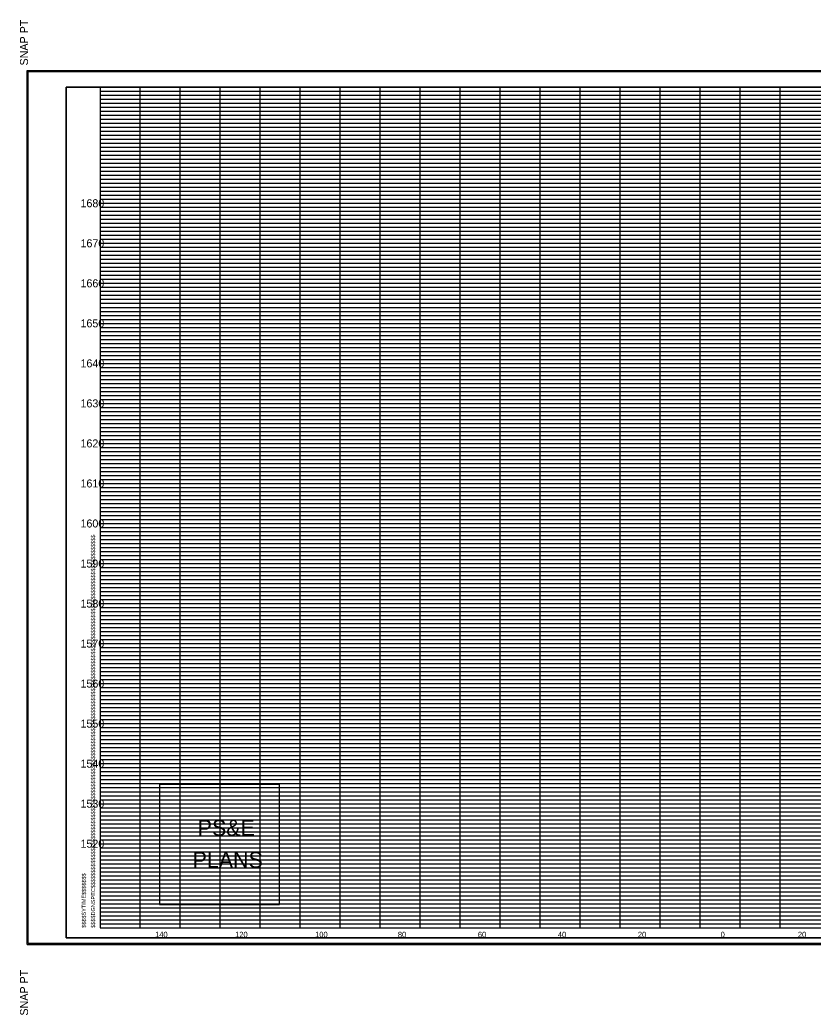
# Model space of a CAD drawing. Extents: x 980 to 1380, y 1248 to 3387.
# Drawn here: x 979.9 to 1178.2, y 1248.2 to 1496.8 of the extents above; entities that cross this region are included whole.
import ezdxf

# ---------------------------------------------------------------- set-up
doc = ezdxf.new("R2010")
doc.units = 0
for name, color, linetype in [('DESIGN - SHEET - Corner Text', 7, 'Continuous'), ('DESIGN - SHEET - Light Grid', 7, 'Continuous'), ('DESIGN - SHEET - Linework', 7, 'Continuous'), ('DESIGN - SHEET - Plot Shape', 7, 'Continuous'), ('DESIGN - TYPICAL - Text', 7, 'Continuous')]:
    doc.layers.add(name, color=color, linetype=linetype)

# ---------------------------------------------------------------- blocks, each defined once
blk = doc.blocks.new('XSTSHT')
at = {"layer": 'DESIGN - SHEET - Light Grid'}
for p, q in [((0, 20.9), (8, 20.9)), ((8, 20.9), (16, 20.9)), ((16, 20.9), (24, 20.9)), ((0, 20.8), (8, 20.8)), ((0, 20.7), (8, 20.7)), ((8, 20.8), (16, 20.8)), ((8, 20.7), (16, 20.7)), ((16, 20.8), (24, 20.8)), ((16, 20.7), (24, 20.7)), ((0, 20.6), (8, 20.6)), ((0, 20.5), (8, 20.5)), ((0, 20.4), (8, 20.4)), ((8, 20.6), (16, 20.6)), ((8, 20.5), (16, 20.5)), ((8, 20.4), (16, 20.4)), ((16, 20.6), (24, 20.6)), ((16, 20.5), (24, 20.5)), ((16, 20.4), (24, 20.4)), ((0, 20.3), (8, 20.3)), ((0, 20.2), (8, 20.2)), ((8, 20.3), (16, 20.3)), ((8, 20.2), (16, 20.2)), ((16, 20.3), (24, 20.3)), ((16, 20.2), (24, 20.2)), ((0, 20.1), (8, 20.1)), ((0, 19.9), (8, 19.9)), ((8, 20.1), (16, 20.1)), ((8, 19.9), (16, 19.9)), ((16, 20.1), (24, 20.1)), ((16, 19.9), (24, 19.9)), ((0, 19.8), (8, 19.8)), ((0, 19.7), (8, 19.7)), ((8, 19.8), (16, 19.8)), ((8, 19.7), (16, 19.7)), ((16, 19.8), (24, 19.8)), ((16, 19.7), (24, 19.7)), ((0, 19.6), (8, 19.6)), ((0, 19.5), (8, 19.5)), ((0, 19.4), (8, 19.4)), ((8, 19.6), (16, 19.6)), ((8, 19.5), (16, 19.5)), ((8, 19.4), (16, 19.4)), ((16, 19.6), (24, 19.6)), ((16, 19.5), (24, 19.5)), ((16, 19.4), (24, 19.4)), ((0, 19.3), (8, 19.3)), ((0, 19.2), (8, 19.2)), ((8, 19.3), (16, 19.3)), ((8, 19.2), (16, 19.2)), ((16, 19.3), (24, 19.3)), ((16, 19.2), (24, 19.2)), ((0, 19.1), (8, 19.1)), ((0, 18.9), (8, 18.9)), ((8, 19.1), (16, 19.1)), ((8, 18.9), (16, 18.9)), ((16, 19.1), (24, 19.1)), ((16, 18.9), (24, 18.9)), ((0, 18.8), (8, 18.8)), ((0, 18.7), (8, 18.7)), ((8, 18.8), (16, 18.8)), ((8, 18.7), (16, 18.7)), ((16, 18.8), (24, 18.8)), ((16, 18.7), (24, 18.7)), ((0, 18.6), (8, 18.6)), ((0, 18.5), (8, 18.5)), ((0, 18.4), (8, 18.4)), ((8, 18.6), (16, 18.6)), ((8, 18.5), (16, 18.5)), ((8, 18.4), (16, 18.4)), ((16, 18.6), (24, 18.6)), ((16, 18.5), (24, 18.5)), ((16, 18.4), (24, 18.4)), ((0, 18.3), (8, 18.3)), ((0, 18.2), (8, 18.2)), ((8, 18.3), (16, 18.3)), ((8, 18.2), (16, 18.2)), ((16, 18.3), (24, 18.3)), ((16, 18.2), (24, 18.2)), ((0, 18.1), (8, 18.1)), ((8, 18.1), (16, 18.1)), ((16, 18.1), (24, 18.1)), ((0, 17.9), (8, 17.9)), ((0, 17.8), (8, 17.8)), ((0, 17.7), (8, 17.7)), ((8, 17.9), (16, 17.9)), ((8, 17.8), (16, 17.8)), ((8, 17.7), (16, 17.7)), ((16, 17.9), (24, 17.9)), ((16, 17.8), (24, 17.8)), ((16, 17.7), (24, 17.7)), ((0, 17.6), (8, 17.6)), ((0, 17.5), (8, 17.5)), ((8, 17.6), (16, 17.6)), ((8, 17.5), (16, 17.5)), ((16, 17.6), (24, 17.6)), ((16, 17.5), (24, 17.5)), ((0, 17.4), (8, 17.4)), ((0, 17.3), (8, 17.3)), ((0, 17.2), (8, 17.2)), ((8, 17.4), (16, 17.4)), ((8, 17.3), (16, 17.3)), ((8, 17.2), (16, 17.2)), ((16, 17.4), (24, 17.4)), ((16, 17.3), (24, 17.3)), ((16, 17.2), (24, 17.2)), ((0, 17.1), (8, 17.1)), ((8, 17.1), (16, 17.1)), ((16, 17.1), (24, 17.1)), ((0, 16.9), (8, 16.9)), ((0, 16.8), (8, 16.8)), ((0, 16.7), (8, 16.7)), ((8, 16.9), (16, 16.9)), ((8, 16.8), (16, 16.8)), ((8, 16.7), (16, 16.7)), ((16, 16.9), (24, 16.9)), ((16, 16.8), (24, 16.8)), ((16, 16.7), (24, 16.7)), ((0, 16.6), (8, 16.6)), ((0, 16.5), (8, 16.5)), ((8, 16.6), (16, 16.6)), ((8, 16.5), (16, 16.5)), ((16, 16.6), (24, 16.6)), ((16, 16.5), (24, 16.5)), ((0, 16.4), (8, 16.4)), ((0, 16.3), (8, 16.3)), ((0, 16.2), (8, 16.2)), ((8, 16.4), (16, 16.4)), ((8, 16.3), (16, 16.3)), ((8, 16.2), (16, 16.2)), ((16, 16.4), (24, 16.4)), ((16, 16.3), (24, 16.3)), ((16, 16.2), (24, 16.2)), ((0, 16.1), (8, 16.1)), ((8, 16.1), (16, 16.1)), ((16, 16.1), (24, 16.1)), ((0, 15.9), (8, 15.9)), ((0, 15.8), (8, 15.8)), ((0, 15.7), (8, 15.7)), ((8, 15.9), (16, 15.9)), ((8, 15.8), (16, 15.8)), ((8, 15.7), (16, 15.7)), ((16, 15.9), (24, 15.9)), ((16, 15.8), (24, 15.8)), ((16, 15.7), (24, 15.7)), ((0, 15.6), (8, 15.6)), ((0, 15.5), (8, 15.5)), ((8, 15.6), (16, 15.6)), ((8, 15.5), (16, 15.5)), ((16, 15.6), (24, 15.6)), ((16, 15.5), (24, 15.5)), ((0, 15.4), (8, 15.4)), ((0, 15.3), (8, 15.3)), ((0, 15.2), (8, 15.2)), ((8, 15.4), (16, 15.4)), ((8, 15.3), (16, 15.3)), ((8, 15.2), (16, 15.2)), ((16, 15.4), (24, 15.4)), ((16, 15.3), (24, 15.3)), ((16, 15.2), (24, 15.2)), ((0, 15.1), (8, 15.1)), ((8, 15.1), (16, 15.1)), ((16, 15.1), (24, 15.1)), ((0, 14.9), (8, 14.9)), ((0, 14.8), (8, 14.8)), ((0, 14.7), (8, 14.7)), ((8, 14.9), (16, 14.9)), ((8, 14.8), (16, 14.8)), ((8, 14.7), (16, 14.7)), ((16, 14.9), (24, 14.9)), ((16, 14.8), (24, 14.8)), ((16, 14.7), (24, 14.7)), ((0, 14.6), (8, 14.6)), ((0, 14.5), (8, 14.5)), ((8, 14.6), (16, 14.6)), ((8, 14.5), (16, 14.5)), ((16, 14.6), (24, 14.6)), ((16, 14.5), (24, 14.5)), ((0, 14.4), (8, 14.4)), ((0, 14.3), (8, 14.3)), ((0, 14.2), (8, 14.2)), ((8, 14.4), (16, 14.4)), ((8, 14.3), (16, 14.3)), ((8, 14.2), (16, 14.2)), ((16, 14.4), (24, 14.4)), ((16, 14.3), (24, 14.3)), ((16, 14.2), (24, 14.2)), ((0, 14.1), (8, 14.1)), ((8, 14.1), (16, 14.1)), ((16, 14.1), (24, 14.1)), ((0, 13.9), (8, 13.9)), ((0, 13.8), (8, 13.8)), ((0, 13.7), (8, 13.7)), ((8, 13.9), (16, 13.9)), ((8, 13.8), (16, 13.8)), ((8, 13.7), (16, 13.7)), ((16, 13.9), (24, 13.9)), ((16, 13.8), (24, 13.8)), ((16, 13.7), (24, 13.7)), ((0, 13.6), (8, 13.6)), ((0, 13.5), (8, 13.5)), ((8, 13.6), (16, 13.6)), ((8, 13.5), (16, 13.5)), ((16, 13.6), (24, 13.6)), ((16, 13.5), (24, 13.5)), ((0, 13.4), (8, 13.4)), ((0, 13.3), (8, 13.3)), ((0, 13.2), (8, 13.2)), ((8, 13.4), (16, 13.4)), ((8, 13.3), (16, 13.3)), ((8, 13.2), (16, 13.2)), ((16, 13.4), (24, 13.4)), ((16, 13.3), (24, 13.3)), ((16, 13.2), (24, 13.2)), ((0, 13.1), (8, 13.1)), ((8, 13.1), (16, 13.1)), ((16, 13.1), (24, 13.1)), ((0, 12.9), (8, 12.9)), ((0, 12.8), (8, 12.8)), ((0, 12.7), (8, 12.7)), ((8, 12.9), (16, 12.9)), ((8, 12.8), (16, 12.8)), ((8, 12.7), (16, 12.7)), ((16, 12.9), (24, 12.9)), ((16, 12.8), (24, 12.8)), ((16, 12.7), (24, 12.7)), ((0, 12.6), (8, 12.6)), ((0, 12.5), (8, 12.5)), ((8, 12.6), (16, 12.6)), ((8, 12.5), (16, 12.5)), ((16, 12.6), (24, 12.6)), ((16, 12.5), (24, 12.5)), ((0, 12.4), (8, 12.4)), ((0, 12.3), (8, 12.3)), ((0, 12.2), (8, 12.2)), ((8, 12.4), (16, 12.4)), ((8, 12.3), (16, 12.3)), ((8, 12.2), (16, 12.2)), ((16, 12.4), (24, 12.4)), ((16, 12.3), (24, 12.3)), ((16, 12.2), (24, 12.2)), ((0, 12.1), (8, 12.1)), ((8, 12.1), (16, 12.1)), ((16, 12.1), (24, 12.1)), ((0, 11.9), (8, 11.9)), ((0, 11.8), (8, 11.8)), ((0, 11.7), (8, 11.7)), ((8, 11.9), (16, 11.9)), ((8, 11.8), (16, 11.8)), ((8, 11.7), (16, 11.7)), ((16, 11.9), (24, 11.9)), ((16, 11.8), (24, 11.8)), ((16, 11.7), (24, 11.7)), ((0, 11.6), (8, 11.6)), ((0, 11.5), (8, 11.5)), ((8, 11.6), (16, 11.6)), ((8, 11.5), (16, 11.5)), ((16, 11.6), (24, 11.6)), ((16, 11.5), (24, 11.5)), ((0, 11.4), (8, 11.4)), ((0, 11.3), (8, 11.3)), ((0, 11.2), (8, 11.2)), ((8, 11.4), (16, 11.4)), ((8, 11.3), (16, 11.3)), ((8, 11.2), (16, 11.2)), ((16, 11.4), (24, 11.4)), ((16, 11.3), (24, 11.3)), ((16, 11.2), (24, 11.2)), ((0, 11.1), (8, 11.1)), ((8, 11.1), (16, 11.1)), ((16, 11.1), (24, 11.1)), ((0, 10.9), (8, 10.9)), ((0, 10.8), (8, 10.8)), ((0, 10.7), (8, 10.7)), ((8, 10.9), (16, 10.9)), ((8, 10.8), (16, 10.8)), ((8, 10.7), (16, 10.7)), ((16, 10.9), (24, 10.9)), ((16, 10.8), (24, 10.8)), ((16, 10.7), (24, 10.7)), ((0, 10.6), (8, 10.6)), ((0, 10.5), (8, 10.5)), ((8, 10.6), (16, 10.6)), ((8, 10.5), (16, 10.5)), ((16, 10.6), (24, 10.6)), ((16, 10.5), (24, 10.5)), ((0, 10.4), (8, 10.4)), ((0, 10.3), (8, 10.3)), ((0, 10.2), (8, 10.2)), ((8, 10.4), (16, 10.4)), ((8, 10.3), (16, 10.3)), ((8, 10.2), (16, 10.2)), ((16, 10.4), (24, 10.4)), ((16, 10.3), (24, 10.3)), ((16, 10.2), (24, 10.2)), ((0, 10.1), (8, 10.1)), ((8, 10.1), (16, 10.1)), ((16, 10.1), (24, 10.1)), ((0, 9.9), (8, 9.9)), ((0, 9.8), (8, 9.8)), ((0, 9.7), (8, 9.7)), ((8, 9.9), (16, 9.9)), ((8, 9.8), (16, 9.8)), ((8, 9.7), (16, 9.7)), ((16, 9.9), (24, 9.9)), ((16, 9.8), (24, 9.8)), ((16, 9.7), (24, 9.7)), ((0, 9.6), (8, 9.6)), ((0, 9.5), (8, 9.5)), ((8, 9.6), (16, 9.6)), ((8, 9.5), (16, 9.5)), ((16, 9.6), (24, 9.6)), ((16, 9.5), (24, 9.5)), ((0, 9.4), (8, 9.4)), ((0, 9.3), (8, 9.3)), ((0, 9.2), (8, 9.2)), ((8, 9.4), (16, 9.4)), ((8, 9.3), (16, 9.3)), ((8, 9.2), (16, 9.2)), ((16, 9.4), (24, 9.4)), ((16, 9.3), (24, 9.3)), ((16, 9.2), (24, 9.2)), ((0, 9.1), (8, 9.1)), ((8, 9.1), (16, 9.1)), ((16, 9.1), (24, 9.1)), ((0, 8.9), (8, 8.9)), ((0, 8.8), (8, 8.8)), ((8, 8.9), (16, 8.9)), ((8, 8.8), (16, 8.8)), ((16, 8.9), (24, 8.9)), ((16, 8.8), (24, 8.8)), ((0, 8.7), (8, 8.7)), ((0, 8.6), (8, 8.6)), ((0, 8.5), (8, 8.5)), ((8, 8.7), (16, 8.7)), ((8, 8.6), (16, 8.6)), ((8, 8.5), (16, 8.5)), ((16, 8.7), (24, 8.7)), ((16, 8.6), (24, 8.6)), ((16, 8.5), (24, 8.5)), ((0, 8.4), (8, 8.4)), ((0, 8.3), (8, 8.3)), ((8, 8.4), (16, 8.4)), ((8, 8.3), (16, 8.3)), ((16, 8.4), (24, 8.4)), ((16, 8.3), (24, 8.3)), ((0, 8.2), (8, 8.2)), ((0, 8.1), (8, 8.1)), ((8, 8.2), (16, 8.2)), ((8, 8.1), (16, 8.1)), ((16, 8.2), (24, 8.2)), ((16, 8.1), (24, 8.1)), ((0, 7.9), (8, 7.9)), ((0, 7.8), (8, 7.8)), ((8, 7.9), (16, 7.9)), ((8, 7.8), (16, 7.8)), ((16, 7.9), (24, 7.9)), ((16, 7.8), (24, 7.8)), ((0, 7.7), (8, 7.7)), ((0, 7.6), (8, 7.6)), ((0, 7.5), (8, 7.5)), ((8, 7.7), (16, 7.7)), ((8, 7.6), (16, 7.6)), ((8, 7.5), (16, 7.5)), ((16, 7.7), (24, 7.7)), ((16, 7.6), (24, 7.6)), ((16, 7.5), (24, 7.5)), ((0, 7.4), (8, 7.4)), ((0, 7.3), (8, 7.3)), ((8, 7.4), (16, 7.4)), ((8, 7.3), (16, 7.3)), ((16, 7.4), (24, 7.4)), ((16, 7.3), (24, 7.3)), ((0, 7.2), (8, 7.2)), ((0, 7.1), (8, 7.1)), ((8, 7.2), (16, 7.2)), ((8, 7.1), (16, 7.1)), ((16, 7.2), (24, 7.2)), ((16, 7.1), (24, 7.1)), ((0, 6.9), (8, 6.9)), ((0, 6.8), (8, 6.8)), ((8, 6.9), (16, 6.9)), ((8, 6.8), (16, 6.8)), ((16, 6.9), (24, 6.9)), ((16, 6.8), (24, 6.8)), ((0, 6.7), (8, 6.7)), ((0, 6.6), (8, 6.6)), ((0, 6.5), (8, 6.5)), ((8, 6.7), (16, 6.7)), ((8, 6.6), (16, 6.6)), ((8, 6.5), (16, 6.5)), ((16, 6.7), (24, 6.7)), ((16, 6.6), (24, 6.6)), ((16, 6.5), (24, 6.5)), ((0, 6.4), (8, 6.4)), ((0, 6.3), (8, 6.3)), ((8, 6.4), (16, 6.4)), ((8, 6.3), (16, 6.3)), ((16, 6.4), (24, 6.4)), ((16, 6.3), (24, 6.3)), ((0, 6.2), (8, 6.2)), ((0, 6.1), (8, 6.1)), ((8, 6.2), (16, 6.2)), ((8, 6.1), (16, 6.1)), ((16, 6.2), (24, 6.2)), ((16, 6.1), (24, 6.1)), ((0, 5.9), (8, 5.9)), ((0, 5.8), (8, 5.8)), ((8, 5.9), (16, 5.9)), ((8, 5.8), (16, 5.8)), ((16, 5.9), (24, 5.9)), ((16, 5.8), (24, 5.8)), ((0, 5.7), (8, 5.7)), ((0, 5.6), (8, 5.6)), ((0, 5.5), (8, 5.5)), ((8, 5.7), (16, 5.7)), ((8, 5.6), (16, 5.6)), ((8, 5.5), (16, 5.5)), ((16, 5.7), (24, 5.7)), ((16, 5.6), (24, 5.6)), ((16, 5.5), (24, 5.5)), ((0, 5.4), (8, 5.4)), ((0, 5.3), (8, 5.3)), ((8, 5.4), (16, 5.4)), ((8, 5.3), (16, 5.3)), ((16, 5.4), (24, 5.4)), ((16, 5.3), (24, 5.3)), ((0, 5.2), (8, 5.2)), ((0, 5.1), (8, 5.1)), ((8, 5.2), (16, 5.2)), ((8, 5.1), (16, 5.1)), ((16, 5.2), (24, 5.2)), ((16, 5.1), (24, 5.1)), ((0, 4.9), (8, 4.9)), ((0, 4.8), (8, 4.8)), ((8, 4.9), (16, 4.9)), ((8, 4.8), (16, 4.8)), ((16, 4.9), (24, 4.9)), ((16, 4.8), (24, 4.8)), ((0, 4.7), (8, 4.7)), ((0, 4.6), (8, 4.6)), ((0, 4.5), (8, 4.5)), ((8, 4.7), (16, 4.7)), ((8, 4.6), (16, 4.6)), ((8, 4.5), (16, 4.5)), ((16, 4.7), (24, 4.7)), ((16, 4.6), (24, 4.6)), ((16, 4.5), (24, 4.5)), ((0, 4.4), (8, 4.4)), ((0, 4.3), (8, 4.3)), ((8, 4.4), (16, 4.4)), ((8, 4.3), (16, 4.3)), ((16, 4.4), (24, 4.4)), ((16, 4.3), (24, 4.3)), ((0, 4.2), (8, 4.2)), ((0, 4.1), (8, 4.1)), ((8, 4.2), (16, 4.2)), ((8, 4.1), (16, 4.1)), ((16, 4.2), (24, 4.2)), ((16, 4.1), (24, 4.1)), ((0, 3.9), (8, 3.9)), ((0, 3.8), (8, 3.8)), ((8, 3.9), (16, 3.9)), ((8, 3.8), (16, 3.8)), ((16, 3.9), (24, 3.9)), ((16, 3.8), (24, 3.8)), ((0, 3.7), (8, 3.7)), ((0, 3.6), (8, 3.6)), ((0, 3.5), (8, 3.5)), ((8, 3.7), (16, 3.7)), ((8, 3.6), (16, 3.6)), ((8, 3.5), (16, 3.5)), ((16, 3.7), (24, 3.7)), ((16, 3.6), (24, 3.6)), ((16, 3.5), (24, 3.5)), ((0, 3.4), (8, 3.4)), ((0, 3.3), (8, 3.3)), ((8, 3.4), (16, 3.4)), ((8, 3.3), (16, 3.3)), ((16, 3.4), (24, 3.4)), ((16, 3.3), (24, 3.3)), ((0, 3.2), (8, 3.2)), ((0, 3.1), (8, 3.1)), ((8, 3.2), (16, 3.2)), ((8, 3.1), (16, 3.1)), ((16, 3.2), (24, 3.2)), ((16, 3.1), (24, 3.1)), ((0, 2.9), (8, 2.9)), ((0, 2.8), (8, 2.8)), ((8, 2.9), (16, 2.9)), ((8, 2.8), (16, 2.8)), ((16, 2.9), (24, 2.9)), ((16, 2.8), (24, 2.8)), ((0, 2.7), (8, 2.7)), ((0, 2.6), (8, 2.6)), ((0, 2.5), (8, 2.5)), ((8, 2.7), (16, 2.7)), ((8, 2.6), (16, 2.6)), ((8, 2.5), (16, 2.5)), ((16, 2.7), (24, 2.7)), ((16, 2.6), (24, 2.6)), ((16, 2.5), (24, 2.5)), ((0, 2.4), (8, 2.4)), ((0, 2.3), (8, 2.3)), ((8, 2.4), (16, 2.4)), ((8, 2.3), (16, 2.3)), ((16, 2.4), (24, 2.4)), ((16, 2.3), (24, 2.3)), ((0, 2.2), (8, 2.2)), ((0, 2.1), (8, 2.1)), ((8, 2.2), (16, 2.2)), ((8, 2.1), (16, 2.1)), ((16, 2.2), (24, 2.2)), ((16, 2.1), (24, 2.1)), ((0, 1.9), (8, 1.9)), ((0, 1.8), (8, 1.8)), ((8, 1.9), (16, 1.9)), ((8, 1.8), (16, 1.8)), ((16, 1.9), (24, 1.9)), ((16, 1.8), (24, 1.8)), ((0, 1.7), (8, 1.7)), ((0, 1.6), (8, 1.6)), ((0, 1.5), (8, 1.5)), ((8, 1.7), (16, 1.7)), ((8, 1.6), (16, 1.6)), ((8, 1.5), (16, 1.5)), ((16, 1.7), (24, 1.7)), ((16, 1.6), (24, 1.6)), ((16, 1.5), (24, 1.5)), ((0, 1.4), (8, 1.4)), ((0, 1.3), (8, 1.3)), ((8, 1.4), (16, 1.4)), ((8, 1.3), (16, 1.3)), ((16, 1.4), (24, 1.4)), ((16, 1.3), (24, 1.3)), ((0, 1.2), (8, 1.2)), ((0, 1.1), (8, 1.1)), ((8, 1.2), (16, 1.2)), ((8, 1.1), (16, 1.1)), ((16, 1.2), (24, 1.2)), ((16, 1.1), (24, 1.1)), ((0, 0.9), (8, 0.9)), ((0, 0.8), (8, 0.8)), ((8, 0.9), (16, 0.9)), ((8, 0.8), (16, 0.8)), ((16, 0.9), (24, 0.9)), ((16, 0.8), (24, 0.8)), ((0, 0.7), (8, 0.7)), ((0, 0.6), (8, 0.6)), ((0, 0.5), (8, 0.5)), ((8, 0.7), (16, 0.7)), ((8, 0.6), (16, 0.6)), ((8, 0.5), (16, 0.5)), ((16, 0.7), (24, 0.7)), ((16, 0.6), (24, 0.6)), ((16, 0.5), (24, 0.5)), ((0, 0.4), (8, 0.4)), ((0, 0.3), (8, 0.3)), ((8, 0.4), (16, 0.4)), ((8, 0.3), (16, 0.3)), ((16, 0.4), (24, 0.4)), ((16, 0.3), (24, 0.3)), ((0, 0.2), (8, 0.2)), ((0, 0.1), (8, 0.1)), ((8, 0.2), (16, 0.2)), ((8, 0.1), (16, 0.1)), ((16, 0.2), (24, 0.2)), ((16, 0.1), (24, 0.1))]:
    blk.add_line(p, q, dxfattribs=at)
at = {"layer": 'DESIGN - SHEET - Linework'}
for p, q in [((-1.823, -0.414), (-1.823, 21.414)), ((-1.823, 21.414), (32.217, 21.414)), ((1, 0), (1, 21)), ((2, 0), (2, 21)), ((3, 0), (3, 21)), ((4, 0), (4, 21)), ((5, 0), (5, 21)), ((6, 0), (6, 21)), ((7, 0), (7, 21)), ((8, 0), (8, 21)), ((9, 0), (9, 21)), ((10, 0), (10, 21)), ((11, 0), (11, 21)), ((12, 0), (12, 21)), ((13, 0), (13, 21)), ((14, 0), (14, 21)), ((15, 0), (15, 21)), ((16, 0), (16, 21)), ((17, 0), (17, 21)), ((0, 20), (28, 20)), ((0, 19), (32, 19)), ((0, 18), (32, 18)), ((0, 17), (32, 17)), ((0, 16), (32, 16)), ((0, 15), (32, 15)), ((0, 14), (32, 14)), ((0, 13), (32, 13)), ((0, 12), (32, 12)), ((0, 11), (32, 11)), ((0, 10), (32, 10)), ((0, 9), (32, 9)), ((0, 8), (32, 8)), ((0, 7), (32, 7)), ((0, 6), (32, 6)), ((0, 5), (32, 5)), ((0, 4), (32, 4)), ((0, 3), (32, 3)), ((0, 2), (32, 2)), ((0, 1), (32, 1)), ((-1.823, -0.414), (32.217, -0.414))]:
    blk.add_line(p, q, dxfattribs=at)
blk.add_lwpolyline([(0, 21), (0, 0), (32, 0), (32, 21), (0, 21)], dxfattribs=at)
at = {"layer": 'DESIGN - SHEET - Plot Shape'}
for points in [[(-1.803, 21.394), (32.197, 21.394), (32.197, -0.394), (-1.803, -0.394)], [(-0.85, 21), (32, 21), (32, -0.25), (-0.85, -0.25)]]:
    blk.add_lwpolyline(points, close=True, dxfattribs=at)
at = {"layer": 'DESIGN - SHEET - Corner Text'}
for s, height, p in [('  SNAP PT', 0.2, (-1.803, 21.394)), ('$$$$DGNSPEC$$$$$$$$$$$$$$$$$$$$$$$$$$$$$$$$$$$$$$$$$$$$$$$$$$$$$$$$$$$$$$$$$$$$$$$$$$$$$$$$$$$$$$$$$$$$$$$$$$$$$$$$$$$$$$$$$$$', 0.100002, (-0.126, 0)), ('$$$$SYTIME$$$$$$$', 0.1, (-0.358, 0)), ('SNAP PT  ', 0.2, (-1.803, -2.194))]:
    blk.add_text(s, height=height, rotation=90, dxfattribs=at).set_placement(p)

msp = doc.modelspace()

# ---------------------------------------------------------------- linework, layer by layer
at = {"layer": 'DESIGN - SHEET - Corner Text'}
msp.add_lwpolyline([(1014.87, 1305.8), (1014.87, 1275.8), (1044.87, 1275.8), (1044.87, 1305.8)], close=True, dxfattribs=at)
at = {"layer": 'DESIGN - SHEET - Plot Shape'}
msp.add_lwpolyline([(991.5, 1267.5), (1320, 1267.5), (1320, 1480), (991.5, 1480)], close=True, dxfattribs=at)

# ---------------------------------------------------------------- block references
at = {"layer": 'DESIGN - TYPICAL - Text', "xscale": 10, "yscale": 10}
msp.add_blockref('XSTSHT', (1000, 1270), dxfattribs=at)

# ---------------------------------------------------------------- texts
at = {"layer": 'DESIGN - SHEET - Corner Text'}
for s, p in [('PS&E', (1024.39, 1292.97)), ('PLANS', (1023.11, 1284.97))]:
    msp.add_text(s, height=4, dxfattribs=at).set_placement(p)
at = {"layer": 'DESIGN - TYPICAL - Text'}
for s, height, p in [('     1680     ', 2, (991.37, 1450)), ('     1670     ', 2, (991.37, 1440)), ('     1660     ', 2, (991.37, 1430)), ('     1650     ', 2, (991.37, 1420)), ('     1640     ', 2, (991.37, 1410)), ('     1630     ', 2, (991.37, 1400)), ('     1620     ', 2, (991.37, 1390)), ('     1610     ', 2, (991.37, 1380)), ('     1600     ', 2, (991.37, 1370)), ('     1590     ', 2, (991.37, 1360)), ('     1580     ', 2, (991.37, 1350)), ('     1570     ', 2, (991.37, 1340)), ('     1560     ', 2, (991.37, 1330)), ('     1550     ', 2, (991.37, 1320)), ('     1540     ', 2, (991.37, 1310)), ('     1530     ', 2, (991.37, 1300)), ('     1520     ', 2, (991.37, 1290)), ('     140     ', 1.4, (1011.14, 1267.6)), ('     120     ', 1.4, (1031.14, 1267.6)), ('     100     ', 1.4, (1051.14, 1267.6)), ('     80     ', 1.4, (1071.82, 1267.6)), ('     60     ', 1.4, (1091.82, 1267.6)), ('     40     ', 1.4, (1111.82, 1267.6)), ('     20     ', 1.4, (1131.82, 1267.6)), ('     0     ', 1.4, (1152.51, 1267.6)), ('     0     ', 1.4, (1152.51, 1267.6)), ('     20     ', 1.4, (1171.82, 1267.6))]:
    msp.add_text(s, height=height, dxfattribs=at).set_placement(p)

doc.saveas('drawing.dxf')
